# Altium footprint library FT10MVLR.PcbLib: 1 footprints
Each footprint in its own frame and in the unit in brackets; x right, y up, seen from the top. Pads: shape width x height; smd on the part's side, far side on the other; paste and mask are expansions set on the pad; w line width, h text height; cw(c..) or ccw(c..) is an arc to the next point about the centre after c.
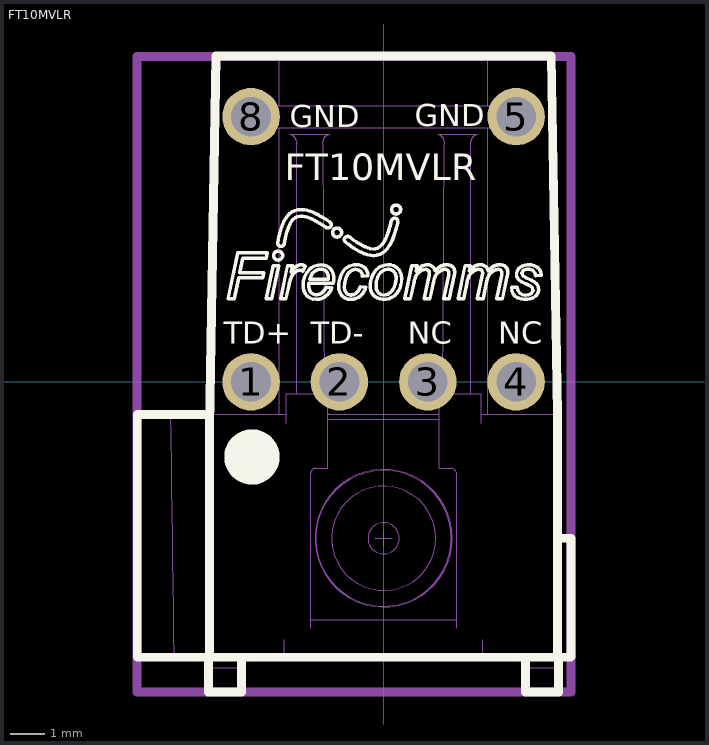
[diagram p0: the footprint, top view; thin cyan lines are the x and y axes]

## FT10MVLR [mil] "10 MBd Vertical Package Non-Inverting TTL"
height 744.09
pads (6):
  round 65 hole 45: 1(-150,0) 2(-50,0) 3(50,0) 4(150,0) 5(150,300) 8(-150,300)
Top Overlay:
  drawing of 818 lines, arcs and shapes, not listed
  text "GND" at 35,289 h25
  text "GND" at -106,288 h25
  text "NC" at 129.92,43.31 h25
  text "NC" at 27.56,43.31 h25
  text "TD-" at -82.68,43.31 h25
  text "TD+" at -181.1,43.31 h25
  text "FT10MVLR" at -112,228 h30
Mechanical 2:
  lines w10: -279,-351 -279,368 212,368 212,-351 -279,-351
Mechanical 19:
  drawing of 829 lines, arcs and shapes, not listed
3D body "Vertical Redlink Connector.stp": height 745.89, standoff -128.11, extent -278.74,-354.01 211.81,365.67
